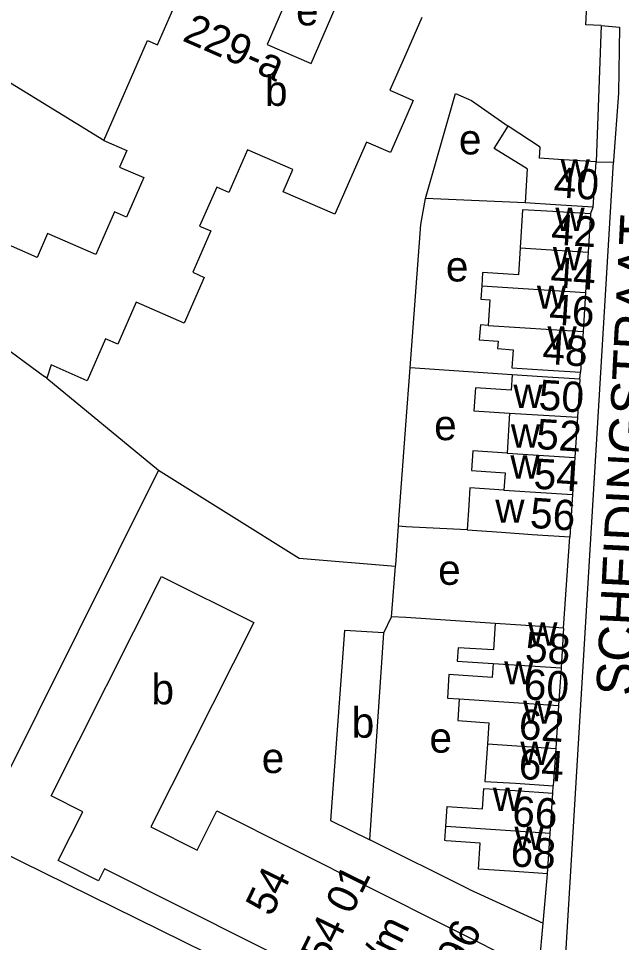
# Model space of a CAD drawing. Extents: x 159700 to 161346, y 381730 to 382922.
# Drawn here: x 160448.9 to 160528.5, y 382017.6 to 382139.7 of the extents above; entities that cross this region are included whole.
import ezdxf

# ---------------------------------------------------------------- set-up
doc = ezdxf.new("R2010")
doc.units = 0
for name, color, linetype in [('BLT_Basislijn', 7, 'Continuous'), ('BLT_Bebouwing', 7, 'Continuous'), ('BLT_Centroide', 7, 'Continuous'), ('BLT_Huisnummer', 7, 'Continuous'), ('BLT_Huisnummer_ tussenligend', 7, 'Continuous'), ('BLT_Huisnummer_reeks', 7, 'Continuous'), ('BLT_Onderverdeling_panden', 7, 'Continuous'), ('BLT_Straatnaam', 7, 'Continuous')]:
    doc.layers.add(name, color=color, linetype=linetype)

msp = doc.modelspace()

# ---------------------------------------------------------------- linework, layer by layer
at = {"layer": 'BLT_Basislijn'}
for p, q in [((160460.12, 382123.53), (160434.39, 382139.32)), ((160525.78, 382138.71), (160525.11, 382120.73)), ((160525.11, 382120.73), (160527.41, 382120.66)), ((160515.74, 382115.32), (160502.61, 382115.9)), ((160524.39, 382113.85), (160524.74, 382114.74)), ((160514.02, 382092.58), (160500.57, 382093.51)), ((160452.61, 382092.17), (160467.35, 382079.98)), ((160522.97, 382092.02), (160523.07, 382092.95)), ((160467.35, 382079.98), (160444.45, 382034.05)), ((160498.66, 382067.49), (160499.02, 382072.59)), ((160520.83, 382059.14), (160521.66, 382071.21)), ((160498.65, 382067.33), (160498.66, 382067.49)), ((160497.08, 382058.49), (160498.11, 382060.64)), ((160519.41, 382037.34), (160519.47, 382038.31)), ((160508.32, 382024.65), (160495.27, 382031.19)), ((160518.43, 382023.65), (160518.71, 382026.69)), ((160508.32, 382024.65), (160518.11, 382020.15)), ((160518.11, 382020.15), (160518.43, 382023.65)), ((160517.46, 382012.97), (160518.11, 382020.15))]:
    msp.add_line(p, q, dxfattribs=at)
for points in [[(160525.78, 382138.71), (160523.76, 382138.82), (160524.67, 382157.12)], [(160525.78, 382138.71), (160528.21, 382138.51), (160528.06, 382129.81), (160527.42, 382120.91), (160527.41, 382120.66)], [(160502.61, 382115.9), (160506.57, 382129.77), (160508.65, 382128.82), (160513.5, 382125.42)], [(160520.83, 382012.11), (160520.92, 382012.42), (160527.41, 382120.66)], [(160500.57, 382093.51), (160501.99, 382112.46), (160502.61, 382115.9)], [(160499.02, 382072.59), (160499.08, 382073.46), (160500, 382085.96), (160500.57, 382093.51)], [(160467.35, 382079.98), (160485.91, 382068.37), (160498.65, 382067.33)], [(160508.12, 382072.1), (160500, 382072.51), (160499.02, 382072.59)], [(160498.11, 382060.64), (160498.14, 382061.17), (160498.65, 382067.33)], [(160511.8, 382059.73), (160500, 382060.52), (160498.11, 382060.64)], [(160498.2, 382004.12), (160443.07, 382031.28), (160444.45, 382034.05)]]:
    msp.add_lwpolyline(points, dxfattribs=at)
at = {"layer": 'BLT_Bebouwing'}
for p, q in [((160524.74, 382114.74), (160525.11, 382120.73)), ((160516.04, 382119.82), (160515.74, 382115.32)), ((160524.39, 382113.85), (160524.07, 382108.8)), ((160430.9, 382107.97), (160452.31, 382092.39)), ((160524.07, 382108.8), (160523.73, 382103.46)), ((160523.73, 382103.46), (160523.41, 382098.32)), ((160523.41, 382098.32), (160523.07, 382092.95)), ((160452.61, 382092.17), (160452.31, 382092.39)), ((160522.97, 382092.02), (160522.65, 382086.98)), ((160522.65, 382086.98), (160522.32, 382081.69)), ((160522.32, 382081.69), (160522.01, 382076.8)), ((160522.01, 382076.8), (160521.66, 382071.21)), ((160520.83, 382059.14), (160520.49, 382053.88)), ((160495.27, 382031.19), (160497.08, 382058.49)), ((160520.49, 382053.88), (160520.17, 382048.93)), ((160520.17, 382048.93), (160519.8, 382043.24)), ((160510.78, 382043.83), (160510.45, 382038.87)), ((160519.8, 382043.24), (160519.47, 382038.31)), ((160519.06, 382032.02), (160519.41, 382037.34)), ((160518.71, 382026.69), (160519.06, 382032.02))]:
    msp.add_line(p, q, dxfattribs=at)
for points in [[(160460.12, 382123.53), (160465.9, 382136.74), (160467.2, 382136.17), (160469.99, 382142.55), (160473.32, 382141.09), (160478.68, 382153.35), (160474.2, 382155.31), (160478.52, 382165.2), (160483.46, 382163.05)], [(160502.1, 382139.78), (160500, 382134.95), (160497.91, 382130.17), (160500.01, 382129.25), (160500.99, 382128.83), (160500, 382126.56), (160497.98, 382121.95), (160494.8, 382123.34), (160490.63, 382113.8), (160483.82, 382116.78), (160485.1, 382119.7), (160479.1, 382122.32), (160476.64, 382116.69), (160475.03, 382117.39), (160472.78, 382112.24), (160474.27, 382111.59), (160471.88, 382106.13), (160473.4, 382105.46), (160470.75, 382099.4), (160464.4, 382102.17), (160461.97, 382096.62), (160460.34, 382097.33), (160457.93, 382091.81), (160453.18, 382093.89), (160452.61, 382092.17)], [(160460.12, 382123.53), (160463.16, 382122.2), (160462.22, 382120.04), (160465.42, 382118.64), (160463.14, 382113.43), (160461.55, 382114.13), (160459.07, 382108.47), (160452.71, 382111.25), (160451.32, 382108.08), (160444.02, 382111.28), (160443.18, 382110.46), (160438.63, 382115.1), (160441.66, 382118.07), (160440.55, 382119.21), (160442.02, 382120.66), (160438.99, 382123.75), (160439, 382125.63), (160436.66, 382128.02), (160434.9, 382128.04), (160433.53, 382126.7), (160430.31, 382129.98)], [(160516.04, 382119.82), (160511.68, 382122.47), (160513.5, 382125.42)], [(160525.11, 382120.73), (160520.12, 382121.04), (160517.63, 382121.2), (160517.73, 382122.64), (160513.5, 382125.42)], [(160524.74, 382114.74), (160519.74, 382115.05), (160515.74, 382115.32)], [(160524.39, 382113.85), (160519.4, 382114.16), (160515.42, 382114.4), (160515.09, 382109.37)], [(160515.09, 382109.37), (160514.86, 382105.8), (160510.13, 382106.09), (160510.02, 382104.33)], [(160510.02, 382104.33), (160509.91, 382102.57), (160511.09, 382102.49), (160510.88, 382099.11)], [(160510.88, 382099.11), (160509.85, 382099.2), (160509.69, 382097.22), (160512.18, 382097.02), (160512.1, 382096.08), (160514.15, 382095.91), (160514, 382093.52), (160518.08, 382093.26), (160523.07, 382092.95)], [(160514.02, 382092.58), (160513.89, 382090.57), (160509.19, 382090.87), (160508.98, 382087.85), (160513.7, 382087.54)], [(160522.97, 382092.02), (160517.98, 382092.33), (160514.02, 382092.58)], [(160513.7, 382087.54), (160513.36, 382082.25)], [(160513.36, 382082.25), (160508.85, 382082.54), (160508.69, 382079.94), (160513.1, 382079.66), (160512.96, 382077.37)], [(160512.96, 382077.37), (160508.46, 382077.65), (160508.32, 382075.36)], [(160508.32, 382075.36), (160508.12, 382072.1)], [(160508.12, 382072.1), (160512.65, 382071.8), (160516.67, 382071.52), (160521.66, 382071.21)], [(160511.8, 382059.73), (160511.57, 382056.25), (160506.9, 382056.55), (160506.78, 382054.78), (160511.54, 382054.47)], [(160520.83, 382059.14), (160515.84, 382059.47), (160511.8, 382059.73)], [(160497.08, 382058.49), (160491.89, 382058.84), (160490.05, 382033.73), (160495.27, 382031.19)], [(160511.54, 382054.47), (160511.42, 382052.62), (160505.69, 382053), (160505.49, 382049.88), (160507.05, 382049.78)], [(160507.05, 382049.78), (160506.86, 382046.91), (160510.96, 382046.64), (160510.78, 382043.83)], [(160510.45, 382038.87), (160514.49, 382038.64), (160519.47, 382038.31)], [(160505.27, 382032.92), (160505.45, 382035.59), (160510.11, 382035.28), (160510.29, 382037.95), (160514.42, 382037.67), (160519.41, 382037.34)], [(160518.71, 382026.69), (160513.72, 382027.02), (160509.61, 382027.28), (160509.82, 382030.75), (160505.33, 382031.05), (160505.13, 382031.07), (160505.27, 382032.92)]]:
    msp.add_lwpolyline(points, dxfattribs=at)
for points in [[(160486.45, 382147.24), (160481.7, 382136.23), (160487.52, 382133.72), (160492.27, 382144.73)], [(160467.76, 382065.94), (160479.92, 382059.86), (160466.35, 382032.89), (160472.46, 382029.82), (160475.06, 382035), (160515.73, 382014.58), (160509.66, 382002.5), (160460.2, 382027.33), (160459.42, 382025.76), (160454.11, 382028.42), (160457.35, 382034.88), (160453.2, 382036.96)]]:
    msp.add_lwpolyline(points, close=True, dxfattribs=at)
at = {"layer": 'BLT_Onderverdeling_panden'}
for p, q in [((160515.09, 382109.37), (160524.07, 382108.8)), ((160510.02, 382104.33), (160523.73, 382103.46)), ((160510.88, 382099.11), (160523.41, 382098.32)), ((160513.7, 382087.54), (160522.65, 382086.98)), ((160513.36, 382082.25), (160522.32, 382081.69)), ((160512.96, 382077.37), (160522.01, 382076.8)), ((160511.54, 382054.47), (160520.49, 382053.88)), ((160507.05, 382049.78), (160520.17, 382048.93)), ((160510.78, 382043.83), (160519.8, 382043.24)), ((160519.06, 382032.02), (160505.27, 382032.92))]:
    msp.add_line(p, q, dxfattribs=at)

# ---------------------------------------------------------------- texts
at = {"layer": 'BLT_Centroide'}
for s, p in [('e', (160485.51, 382138.74)), ('b', (160481.41, 382128.12)), ('e', (160507.01, 382121.7)), ('w', (160520.43, 382118)), ('w', (160519.74, 382111.59)), ('w', (160519.41, 382106.41)), ('e', (160505.29, 382104.92)), ('w', (160517.3, 382101.31)), ('w', (160518.7, 382095.91)), ('w', (160514.2, 382088.23)), ('e', (160503.74, 382083.96)), ('w', (160513.87, 382082.97)), ('w', (160513.8, 382078.88)), ('w', (160511.81, 382073.05)), ('e', (160504.27, 382064.85)), ('w', (160516.15, 382056.81)), ('w', (160512.98, 382051.69)), ('b', (160466.42, 382049.07)), ('w', (160515.48, 382046.5)), ('b', (160492.86, 382044.66)), ('e', (160503.12, 382042.68)), ('e', (160480.98, 382039.99)), ('w', (160515.12, 382041.06)), ('w', (160511.49, 382034.97)), ('w', (160514.34, 382029.84))]:
    msp.add_text(s, height=4, dxfattribs=at).set_placement(p)
at = {"layer": 'BLT_Huisnummer'}
for s, rotation, p in [('40', 356.2011, (160519.43, 382116.07)), ('44', 356.3815, (160519.02, 382104.18)), ('48', 356.3879, (160517.96, 382094.05)), ('52', 356.3964, (160517.13, 382082.81)), ('56', 356.1111, (160516.31, 382072.4)), ('58', 356.2671, (160515.66, 382054.68)), ('62', 356.2698, (160514.83, 382044.47)), ('68', 356.2728, (160513.75, 382027.69))]:
    msp.add_text(s, height=4, rotation=rotation, dxfattribs=at).set_placement(p)
at = {"layer": 'BLT_Huisnummer_ tussenligend'}
for s, rotation, p in [('42', 356.2011, (160519.11, 382109.84)), ('46', 356.3815, (160518.85, 382099.27)), ('50', 356.3879, (160517.46, 382087.98)), ('54', 356.3964, (160516.79, 382077.57)), ('60', 356.2671, (160515.48, 382049.76)), ('64', 356.2698, (160514.82, 382039.23)), ('66', 356.2614, (160513.96, 382032.99))]:
    msp.add_text(s, height=4, rotation=rotation, dxfattribs=at).set_placement(p)
at = {"layer": 'BLT_Huisnummer_reeks'}
for s, rotation, p in [('229-a', 336.3815, (160470.36, 382136.78)), ('54', 63.8753, (160482.26, 382020.9)), ('54 01', 63.8753, (160489.55, 382014.48)), ('t/m', 63.8753, (160497.32, 382013.14)), ('54 96', 63.8753, (160504.21, 382007.25))]:
    msp.add_text(s, height=4, rotation=rotation, dxfattribs=at).set_placement(p)
at = {"layer": 'BLT_Straatnaam'}
msp.add_text('SCHEIDINGSTRAAT', height=4.9999, rotation=87.1045, dxfattribs=at).set_placement((160530.11, 382050.11))

doc.saveas('drawing.dxf')
